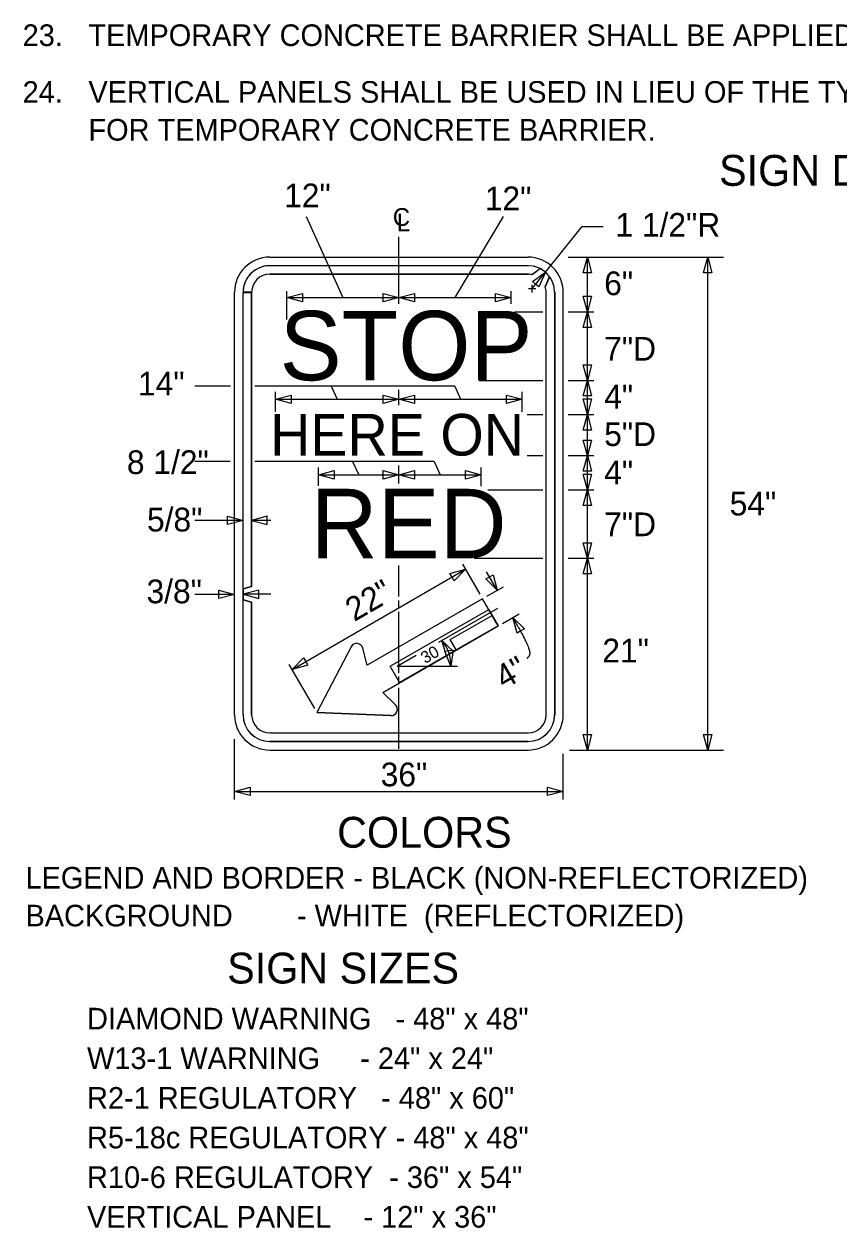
# Model space of a CAD drawing. Extents: x 16520 to 18479, y 5662 to 6927.
# Drawn here: x 17776.7 to 18093.2, y 5948.1 to 6415.8 of the extents above; entities that cross this region are included whole.
import ezdxf

# ---------------------------------------------------------------- set-up
doc = ezdxf.new("R2010")
doc.units = 0
for name, color, linetype in [('MT_SCRATCH_LEVEL_A', 7, 'Continuous'), ('TRAFFIC_SIGNS_PR', 7, 'Continuous'), ('TYPICAL_TEXT_DIMEN_EX', 7, 'Continuous'), ('TYPICAL_TEXT_DIMEN_PR', 7, 'Continuous')]:
    doc.layers.add(name, color=color, linetype=linetype)

msp = doc.modelspace()

# ---------------------------------------------------------------- linework, layer by layer
at = {"layer": 'MT_SCRATCH_LEVEL_A'}
for p, q in [((17922.3, 6307.14), (17922.3, 6333.18)), ((17922.3, 6267.68), (17922.3, 6273.69)), ((17922.3, 6237.32), (17922.3, 6244.25)), ((17922.3, 6193.35), (17922.3, 6205.49)), ((17922.3, 6188.92), (17922.3, 6191.87)), ((17922.3, 6163.79), (17922.3, 6187.44)), ((17922.3, 6159.36), (17922.3, 6162.32)), ((17922.3, 6134.24), (17922.3, 6157.88))]:
    msp.add_line(p, q, dxfattribs=at)
at = {"layer": 'TRAFFIC_SIGNS_PR'}
for p, q in [((17872.12, 6325.27), (17972.55, 6325.27)), ((17872.12, 6321.95), (17872.65, 6321.95)), ((17872.65, 6321.95), (17972.47, 6321.95)), ((17872.65, 6321.93), (17972.47, 6321.95)), ((17977.27, 6320.83), (17974.08, 6318.36)), ((17977.27, 6320.83), (17974.33, 6318.69)), ((17872.12, 6318.62), (17972.57, 6318.62)), ((17972.57, 6318.62), (17872.12, 6318.62)), ((17979.08, 6313.77), (17980.85, 6317.7)), ((17980.62, 6317.24), (17979.08, 6313.77)), ((17858.46, 6147.28), (17858.46, 6311.6)), ((17861.78, 6311.6), (17865.1, 6311.6)), ((17865.11, 6311.6), (17861.78, 6311.6)), ((17861.78, 6147.42), (17861.78, 6311.53)), ((17865.1, 6311.53), (17861.78, 6311.53)), ((17865.1, 6197.27), (17865.1, 6311.53)), ((17979.48, 6147.42), (17979.48, 6311.6)), ((17979.48, 6147.42), (17979.48, 6311.6)), ((17982.81, 6147.42), (17982.81, 6311.6)), ((17982.81, 6311.6), (17982.81, 6147.42)), ((17986.14, 6147.42), (17986.14, 6311.6)), ((17861.79, 6196.38), (17865.1, 6197.27)), ((17861.79, 6193.07), (17861.79, 6195.38)), ((17865.1, 6191.18), (17861.79, 6192.07)), ((17865.1, 6147.42), (17865.1, 6191.18)), ((17954.82, 6192.53), (17910.01, 6166.66)), ((17960.9, 6182), (17954.82, 6192.53)), ((17916.09, 6156.13), (17960.9, 6182)), ((17903.76, 6173.84), (17890.48, 6148.36)), ((17910.01, 6166.66), (17908.27, 6173.33)), ((17920.99, 6151.28), (17916.09, 6156.13)), ((17890.48, 6148.36), (17919.18, 6147.13)), ((17872.12, 6140.4), (17972.52, 6140.4)), ((17872.12, 6140.4), (17972.52, 6140.4)), ((17872.12, 6137.08), (17972.47, 6137.08)), ((17972.47, 6137.08), (17872.12, 6137.08)), ((17872.12, 6133.75), (17930.99, 6133.75)), ((17872.12, 6133.75), (17930.99, 6133.75)), ((17930.99, 6133.75), (17972.47, 6133.75))]:
    msp.add_line(p, q, dxfattribs=at)
msp.add_lwpolyline([(17861.78, 6147.42), (17861.78, 6311.53), (17865.1, 6311.53), (17865.1, 6197.27), (17861.79, 6196.38), (17861.79, 6192.07), (17865.1, 6191.18), (17865.1, 6147.42)], dxfattribs=at)
for points in [[(17960.9, 6182), (17922.52, 6160.01), (17918.9, 6166.33), (17957.28, 6188.32)], [(17960.9, 6182), (17944.56, 6172.65), (17942.24, 6176.7), (17958.58, 6186.05)]]:
    msp.add_lwpolyline(points, close=True, dxfattribs=at)
for centre, radius, start, end in [((17872.12, 6311.6), 13.67, 90, 180), ((17972.46, 6311.6), 13.67, 0, 90), ((17872.12, 6311.6), 10.34, 90, 180), ((17872.12, 6311.6), 10.34, 87.0749, 180), ((17972.46, 6311.6), 10.34, 0.0011, 90), ((17972.46, 6311.6), 10.34, 0, 90), ((17965.42, 6303.66), 20.86, 42.2917, 55.3821), ((17972.46, 6311.6), 10.34, 42.6036, 55.6914), ((17872.12, 6311.6), 7.02, 90, 180), ((17872.12, 6311.6), 7.02, 90, 180), ((17972.46, 6311.6), 7.02, 76.1968, 90), ((17972.68, 6314.86), 3.76, 68.3136, 91.7829), ((17975.26, 6311.94), 4.24, 355.4085, 25.5399), ((17972.46, 6311.6), 7.02, 0.0011, 18.4463), ((17905.91, 6172.71), 2.43, 14.678, 152.4708), ((17919.28, 6149.56), 2.43, 267.5292, 45.322), ((17872.12, 6147.42), 13.67, 180, 270), ((17872.12, 6147.42), 10.34, 180, 270), ((17872.12, 6147.42), 10.35, 180, 270), ((17872.12, 6147.42), 7.02, 180, 270), ((17872.12, 6147.42), 7.02, 180, 270), ((17972.46, 6147.42), 10.34, 270, 0), ((17972.46, 6147.42), 7.02, 270, 0), ((17972.46, 6147.42), 13.67, 270, 0), ((17972.46, 6147.42), 10.35, 270, 0), ((17972.46, 6147.42), 7.02, 270.4693, 0)]:
    msp.add_arc(centre, radius, start, end, dxfattribs=at)
at = {"layer": 'TYPICAL_TEXT_DIMEN_EX'}
for p, q in [((17903.76, 6173.84), (17890.48, 6148.36)), ((17910.01, 6166.66), (17908.27, 6173.33)), ((17916.1, 6156.13), (17921, 6151.28)), ((17919.18, 6147.12), (17890.48, 6148.36))]:
    msp.add_line(p, q, dxfattribs=at)
for centre, start, end in [((17905.91, 6172.71), 14.6782, 152.471), ((17919.29, 6149.56), 267.5295, 45.3222)]:
    msp.add_arc(centre, 2.43, start, end, dxfattribs=at)
at = {"layer": 'TYPICAL_TEXT_DIMEN_PR'}
for p, q in [((17886.21, 6341.01), (17900.52, 6309.57)), ((17962.76, 6341.01), (17944.07, 6309.57)), ((17979.22, 6319.44), (17993.5, 6337.13)), ((17993.5, 6337.13), (18001.59, 6337.13)), ((17988.05, 6325.27), (18048.37, 6325.27)), ((17993.87, 6319.2), (17995.5, 6325.27)), ((17995.5, 6303.99), (17995.5, 6325.27)), ((17995.5, 6325.27), (17997.12, 6319.2)), ((18040.65, 6319.2), (18042.27, 6325.27)), ((18042.27, 6133.75), (18042.27, 6325.27)), ((18042.27, 6325.27), (18043.9, 6319.2)), ((17974.06, 6313.04), (17979.22, 6319.44)), ((17974.15, 6315.74), (17979.22, 6319.44)), ((17979.22, 6319.44), (17976.68, 6313.69)), ((17975.41, 6314.71), (17974.15, 6315.74)), ((17976.68, 6313.69), (17975.41, 6314.71)), ((17995.5, 6319.2), (17993.87, 6319.2)), ((17997.12, 6319.2), (17995.5, 6319.2)), ((18042.27, 6319.2), (18040.65, 6319.2)), ((18043.9, 6319.2), (18042.27, 6319.2)), ((17878.74, 6300.98), (17878.74, 6312.05)), ((17878.74, 6309.57), (17884.8, 6311.19)), ((17884.8, 6311.19), (17884.8, 6309.57)), ((17916.23, 6309.57), (17916.23, 6311.19)), ((17916.23, 6311.19), (17922.3, 6309.57)), ((17922.3, 6309.57), (17928.36, 6311.19)), ((17928.36, 6311.19), (17928.36, 6309.57)), ((17959.78, 6309.57), (17959.78, 6311.19)), ((17959.78, 6311.19), (17965.85, 6309.57)), ((17959.78, 6309.57), (17959.78, 6311.19)), ((17959.78, 6311.19), (17965.85, 6309.57)), ((17965.85, 6307.14), (17965.85, 6312.05)), ((17972.58, 6313.04), (17975.54, 6313.04)), ((17974.06, 6311.56), (17974.06, 6314.51)), ((17995.5, 6303.99), (17993.87, 6310.06)), ((17993.87, 6310.06), (17995.5, 6310.06)), ((17995.5, 6310.06), (17997.12, 6310.06)), ((17997.12, 6310.06), (17995.5, 6303.99)), ((17878.74, 6309.57), (17922.3, 6309.57)), ((17884.8, 6307.94), (17878.74, 6309.57)), ((17884.8, 6309.57), (17884.8, 6307.94)), ((17922.3, 6309.57), (17916.23, 6307.94)), ((17916.23, 6307.94), (17916.23, 6309.57)), ((17922.3, 6309.57), (17965.85, 6309.57)), ((17928.36, 6307.94), (17922.3, 6309.57)), ((17928.36, 6309.57), (17928.36, 6307.94)), ((17965.85, 6309.57), (17959.78, 6307.94)), ((17959.78, 6307.94), (17959.78, 6309.57)), ((17965.85, 6309.57), (17959.78, 6307.94)), ((17959.78, 6307.94), (17959.78, 6309.57)), ((17967.19, 6303.99), (17978.2, 6303.99)), ((17988.05, 6303.99), (17997.98, 6303.99)), ((17993.87, 6297.93), (17995.5, 6303.99)), ((17995.5, 6277.39), (17995.5, 6303.99)), ((17995.5, 6303.99), (17997.12, 6297.93)), ((17995.5, 6297.93), (17993.87, 6297.93)), ((17997.12, 6297.93), (17995.5, 6297.93)), ((17995.5, 6277.39), (17993.87, 6283.46)), ((17993.87, 6283.46), (17995.5, 6283.46)), ((17995.5, 6283.46), (17997.12, 6283.46)), ((17997.12, 6283.46), (17995.5, 6277.39)), ((17953.45, 6277.39), (17978.2, 6277.39)), ((17988.05, 6277.39), (17997.98, 6277.39)), ((17993.87, 6271.32), (17995.5, 6277.39)), ((17995.5, 6264.09), (17995.5, 6277.39)), ((17995.5, 6277.39), (17997.12, 6271.32)), ((17856.87, 6275.15), (17843.07, 6275.15)), ((17944.01, 6275.15), (17866.39, 6275.15)), ((17874.42, 6265.2), (17874.42, 6272.87)), ((17895.99, 6275.15), (17898.35, 6270.01)), ((17944.01, 6275.15), (17946.23, 6270.01)), ((17970.17, 6265.2), (17970.17, 6272.87)), ((17874.42, 6270.01), (17880.48, 6271.64)), ((17874.42, 6270.01), (17922.3, 6270.01)), ((17880.48, 6268.39), (17874.42, 6270.01)), ((17880.48, 6271.64), (17880.48, 6270.01)), ((17880.48, 6270.01), (17880.48, 6268.39)), ((17916.23, 6270.01), (17916.23, 6271.64)), ((17916.23, 6271.64), (17922.3, 6270.01)), ((17922.3, 6270.01), (17916.23, 6268.39)), ((17916.23, 6268.39), (17916.23, 6270.01)), ((17922.3, 6270.01), (17928.36, 6271.64)), ((17922.3, 6270.01), (17970.17, 6270.01)), ((17928.36, 6268.39), (17922.3, 6270.01)), ((17928.36, 6271.64), (17928.36, 6270.01)), ((17928.36, 6270.01), (17928.36, 6268.39)), ((17964.11, 6270.01), (17964.11, 6271.64)), ((17964.11, 6271.64), (17970.17, 6270.01)), ((17970.17, 6270.01), (17964.11, 6268.39)), ((17964.11, 6268.39), (17964.11, 6270.01)), ((17995.5, 6271.32), (17993.87, 6271.32)), ((17995.5, 6264.09), (17993.87, 6270.16)), ((17993.87, 6270.16), (17995.5, 6270.16)), ((17997.12, 6271.32), (17995.5, 6271.32)), ((17995.5, 6270.16), (17997.12, 6270.16)), ((17997.12, 6270.16), (17995.5, 6264.09)), ((17972.18, 6264.09), (17978.2, 6264.09)), ((17988.05, 6264.09), (17997.98, 6264.09)), ((17993.87, 6258.03), (17995.5, 6264.09)), ((17995.5, 6248.13), (17995.5, 6264.09)), ((17995.5, 6264.09), (17997.12, 6258.03)), ((17995.5, 6258.03), (17993.87, 6258.03)), ((17995.5, 6248.13), (17993.87, 6254.2)), ((17993.87, 6254.2), (17995.5, 6254.2)), ((17997.12, 6258.03), (17995.5, 6258.03)), ((17995.5, 6254.2), (17997.12, 6254.2)), ((17997.12, 6254.2), (17995.5, 6248.13)), ((17856.7, 6245.88), (17843.07, 6245.88)), ((17936, 6245.88), (17866.39, 6245.88)), ((17904.28, 6245.88), (17906.67, 6240.67)), ((17936, 6245.88), (17938.26, 6240.67)), ((17972.18, 6248.13), (17978.2, 6248.13)), ((17988.05, 6248.13), (17997.98, 6248.13)), ((17993.87, 6242.07), (17995.5, 6248.13)), ((17995.5, 6234.83), (17995.5, 6248.13)), ((17995.5, 6248.13), (17997.12, 6242.07)), ((17891.04, 6236.44), (17891.04, 6243.53)), ((17891.04, 6240.67), (17897.11, 6242.3)), ((17891.04, 6240.67), (17922.3, 6240.67)), ((17897.11, 6239.05), (17891.04, 6240.67)), ((17897.11, 6242.3), (17897.11, 6240.67)), ((17897.11, 6240.67), (17897.11, 6239.05)), ((17916.23, 6240.67), (17916.23, 6242.3)), ((17916.23, 6242.3), (17922.3, 6240.67)), ((17922.3, 6240.67), (17916.23, 6239.05)), ((17916.23, 6239.05), (17916.23, 6240.67)), ((17922.3, 6240.67), (17928.36, 6242.3)), ((17922.3, 6240.67), (17954.22, 6240.67)), ((17928.36, 6239.05), (17922.3, 6240.67)), ((17928.36, 6242.3), (17928.36, 6240.67)), ((17928.36, 6240.67), (17928.36, 6239.05)), ((17948.15, 6240.67), (17948.15, 6242.3)), ((17948.15, 6242.3), (17954.22, 6240.67)), ((17954.22, 6240.67), (17948.15, 6239.05)), ((17948.15, 6239.05), (17948.15, 6240.67)), ((17954.22, 6236.22), (17954.22, 6243.53)), ((17995.5, 6242.07), (17993.87, 6242.07)), ((17995.5, 6234.83), (17993.87, 6240.9)), ((17993.87, 6240.9), (17995.5, 6240.9)), ((17997.12, 6242.07), (17995.5, 6242.07)), ((17995.5, 6240.9), (17997.12, 6240.9)), ((17997.12, 6240.9), (17995.5, 6234.83)), ((17956.81, 6234.83), (17978.2, 6234.83)), ((17988.05, 6234.83), (17997.98, 6234.83)), ((17993.87, 6228.77), (17995.5, 6234.83)), ((17995.5, 6208.23), (17995.5, 6234.83)), ((17995.5, 6234.83), (17997.12, 6228.77)), ((17995.5, 6228.77), (17993.87, 6228.77)), ((17997.12, 6228.77), (17995.5, 6228.77)), ((17861.79, 6222.98), (17843.07, 6222.98)), ((17855.72, 6222.98), (17855.72, 6224.6)), ((17855.72, 6224.6), (17861.79, 6222.98)), ((17861.79, 6222.98), (17855.72, 6221.35)), ((17855.72, 6221.35), (17855.72, 6222.98)), ((17871.17, 6224.6), (17865.1, 6222.98)), ((17865.1, 6222.98), (17871.17, 6221.35)), ((17872.58, 6222.98), (17865.1, 6222.98)), ((17871.17, 6222.98), (17871.17, 6224.6)), ((17871.17, 6221.35), (17871.17, 6222.98)), ((17995.5, 6208.23), (17993.87, 6214.3)), ((17993.87, 6214.3), (17995.5, 6214.3)), ((17995.5, 6214.3), (17997.12, 6214.3)), ((17997.12, 6214.3), (17995.5, 6208.23)), ((17951.55, 6208.23), (17978.2, 6208.23)), ((17988.05, 6208.23), (17997.98, 6208.23)), ((17993.87, 6202.17), (17995.5, 6208.23)), ((17995.5, 6133.75), (17995.5, 6208.23)), ((17995.5, 6208.23), (17997.12, 6202.17)), ((17880.83, 6165.08), (17948.21, 6203.98)), ((17942.14, 6202.36), (17948.21, 6203.98)), ((17948.21, 6203.98), (17943.77, 6199.54)), ((17953.8, 6194.3), (17947.08, 6205.94)), ((17960.49, 6195.81), (17956.33, 6203.01)), ((17942.95, 6200.95), (17942.14, 6202.36)), ((17943.77, 6199.54), (17942.95, 6200.95)), ((17956.05, 6200.25), (17957.46, 6201.06)), ((17960.49, 6195.81), (17956.05, 6200.25)), ((17957.46, 6201.06), (17958.87, 6201.88)), ((17958.87, 6201.88), (17960.49, 6195.81)), ((17995.5, 6202.17), (17993.87, 6202.17)), ((17997.12, 6202.17), (17995.5, 6202.17)), ((17858.46, 6194.24), (17843.07, 6194.24)), ((17852.39, 6194.24), (17852.39, 6195.86)), ((17852.39, 6195.86), (17858.46, 6194.24)), ((17858.46, 6194.24), (17852.39, 6192.61)), ((17852.39, 6192.61), (17852.39, 6194.24)), ((17867.86, 6195.91), (17861.79, 6194.28)), ((17861.79, 6194.28), (17867.86, 6192.66)), ((17872.58, 6194.28), (17861.79, 6194.28)), ((17867.86, 6194.28), (17867.86, 6195.91)), ((17867.86, 6192.66), (17867.86, 6194.28)), ((17956.5, 6193.5), (17962.9, 6197.2)), ((17937.82, 6175.7), (17960.7, 6188.91)), ((17962.58, 6182.97), (17968.98, 6186.66)), ((17968.66, 6181.66), (17966.57, 6185.28)), ((17968.2, 6179.21), (17966.57, 6185.28)), ((17966.57, 6185.28), (17971.02, 6180.84)), ((17969.61, 6180.02), (17968.2, 6179.21)), ((17971.02, 6180.84), (17969.61, 6180.02)), ((17940.78, 6170.35), (17938.97, 6176.36)), ((17938.97, 6176.36), (17943.54, 6172.06)), ((17921.62, 6166.34), (17928.98, 6170.59)), ((17940.18, 6172.21), (17941.8, 6172.38)), ((17942.42, 6166.34), (17940.18, 6172.21)), ((17942.16, 6171.2), (17940.78, 6170.35)), ((17941.8, 6172.38), (17943.42, 6172.54)), ((17943.54, 6172.06), (17942.16, 6171.2)), ((17943.42, 6172.54), (17942.42, 6166.34)), ((17889.61, 6149.87), (17879.69, 6167.04)), ((17880.83, 6165.08), (17885.27, 6169.52)), ((17886.89, 6166.71), (17880.83, 6165.08)), ((17885.27, 6169.52), (17886.08, 6168.12)), ((17886.08, 6168.12), (17886.89, 6166.71)), ((17921.62, 6166.34), (17945.06, 6166.34)), ((17858.46, 6114.57), (17858.46, 6137.91)), ((17995.5, 6133.75), (17993.87, 6139.82)), ((17993.87, 6139.82), (17995.5, 6139.82)), ((17995.5, 6139.82), (17997.12, 6139.82)), ((17997.12, 6139.82), (17995.5, 6133.75)), ((18042.27, 6133.75), (18040.65, 6139.82)), ((18040.65, 6139.82), (18042.27, 6139.82)), ((18042.27, 6139.82), (18043.9, 6139.82)), ((18043.9, 6139.82), (18042.27, 6133.75)), ((17988.58, 6133.75), (18048.37, 6133.75)), ((17986.14, 6114.57), (17986.14, 6132.23)), ((17858.46, 6117.65), (17864.52, 6119.28)), ((17864.52, 6119.28), (17864.52, 6117.65)), ((17980.07, 6117.65), (17980.07, 6119.28)), ((17980.07, 6119.28), (17986.14, 6117.65)), ((17858.46, 6117.65), (17986.14, 6117.65)), ((17864.52, 6116.03), (17858.46, 6117.65)), ((17864.52, 6117.65), (17864.52, 6116.03)), ((17986.14, 6117.65), (17980.07, 6116.03)), ((17980.07, 6116.03), (17980.07, 6117.65))]:
    msp.add_line(p, q, dxfattribs=at)
msp.add_arc((17928.06, 6167), 14.37, 357.3664, 40.6242, dxfattribs=at)
msp.add_open_spline([(17968.66, 6181.66), (17971.82, 6175.77), (17973.52, 6170.98), (17972.01, 6169.29), (17972.01, 6169.29)], degree=2, dxfattribs=at)

# ---------------------------------------------------------------- texts
at = {"layer": 'TYPICAL_TEXT_DIMEN_EX'}
for s, height, p in [('STOP', 26.972, (17875.97, 6277.41)), ('HERE ON', 16.181, (17872.28, 6248.16)), ('RED', 26.968, (17887.99, 6208.28))]:
    msp.add_text(s, height=height, dxfattribs=at).set_placement(p)
at = {"layer": 'TYPICAL_TEXT_DIMEN_PR'}
for s, height, p in [('23.', 8.4, (17776.14, 6407.29)), ('TEMPORARY CONCRETE BARRIER SHALL BE APPLIED AS PER THE CURRENT STANDARD PLAN.', 8.4, (17801.7, 6407.29)), ('24.', 8.4, (17776.13, 6385.24)), ('VERTICAL PANELS SHALL BE USED IN LIEU OF THE TYPE B HIGH INTENSITY LIGHT SHOWN IN THE STANDARD PLAN ', 8.4, (17801.7, 6385.24)), ('FOR TEMPORARY CONCRETE BARRIER.', 8.4, (17801.7, 6370.54)), ('SIGN DETAIL', 12, (18046.66, 6352.97)), ('12" ', 9.222, (17877.72, 6344.6)), ('12"', 9.222, (17955.66, 6343.48)), ('1 1/2"R', 9.222, (18006.39, 6333.19)), ('6"', 9.222, (18002.04, 6310.47)), ('7"D', 9.222, (18002.04, 6285.04)), ('14"', 9.222, (17820.96, 6271.52)), ('4"', 9.222, (18002.04, 6266.44)), ('5"D', 9.222, (18002.04, 6251.87)), ('8 1/2"', 9.222, (17816.64, 6240.97)), ('4"', 9.222, (18002.04, 6236.98)), ('54"', 9.222, (18050.78, 6224.89)), ('5/8"', 9.222, (17824.44, 6218.67)), ('7"D', 9.222, (18002.04, 6216.83)), ('3/8"', 9.222, (17824.26, 6190.77)), ('21"', 9.222, (18001.32, 6167.78)), ('36" ', 9.222, (17915.22, 6119.64)), ('COLORS', 12, (17898.31, 6095.78)), ('LEGEND AND BORDER - BLACK (NON-REFLECTORIZED)', 8.4, (17777.24, 6079.92)), ('BACKGROUND        - WHITE  (REFLECTORIZED)', 8.4, (17777.24, 6065.22)), ('SIGN SIZES', 12, (17855.59, 6043.03)), ('DIAMOND WARNING   - 48" x 48"', 8.4, (17801.17, 6025.18)), ('W13-1 WARNING     - 24" x 24"', 8.4, (17801.17, 6009.78)), ('R2-1 REGULATORY   - 48" x 60"', 8.4, (17801.17, 5994.38)), ('R5-18c REGULATORY - 48" x 48"', 8.4, (17801.17, 5978.98)), ('R10-6 REGULATORY  - 36" x 54"', 8.4, (17801.17, 5963.58)), ('VERTICAL PANEL    - 12" x 36"', 8.4, (17801.17, 5948.18))]:
    msp.add_text(s, height=height, dxfattribs=at).set_placement(p)
for s, height, rotation, p in [('C', 6.93, 0, (17919.93, 6337.38)), ('L', 6.93, 0, (17921.49, 6335.26)), ('22"', 9.222, 29.9375, (17904.96, 6183.46)), ('30', 4.618, 30, (17932.49, 6167.16)), ('4"', 9.222, 29.9998, (17963.15, 6157.13))]:
    msp.add_text(s, height=height, rotation=rotation, dxfattribs=at).set_placement(p)

doc.saveas('drawing.dxf')
